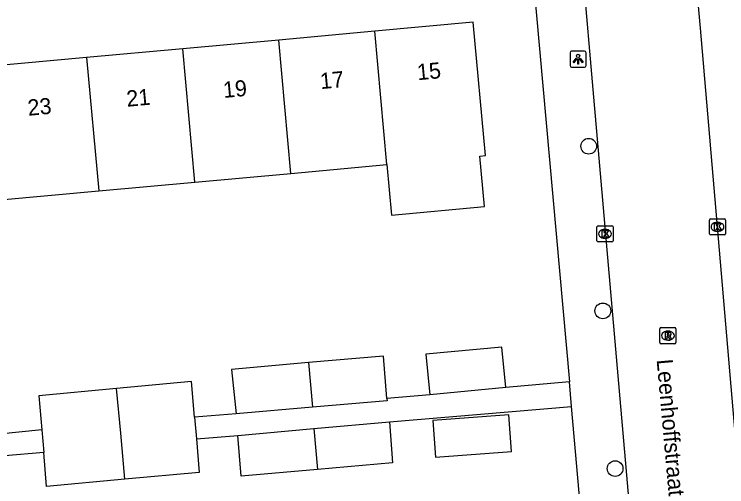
# Model space of a CAD drawing. Extents: x 160557 to 161245, y 385330 to 386505.
# Drawn here: x 161028.26 to 161072.59, y 385585.88 to 385615.29 of the extents above; entities that cross this region are included whole.
import ezdxf

# ---------------------------------------------------------------- set-up
doc = ezdxf.new("R2010")
doc.units = 0
for name, color, linetype in [('IMGEO_Boom', 7, 'Continuous'), ('IMGEO_Kolk', 7, 'Continuous'), ('IMGEO_Lichtpunt', 7, 'Continuous'), ('IMGEO_Openbare_ruimte_label', 7, 'Continuous'), ('IMGEO_Pand', 7, 'Continuous'), ('IMGEO_Pand_nummerreeks', 7, 'Continuous'), ('IMGEO_Rijbaan_lokaal_open', 7, 'Continuous'), ('IMGEO_Rioolput', 7, 'Continuous'), ('IMGEO_Voetpad_open', 7, 'Continuous')]:
    doc.layers.add(name, color=color, linetype=linetype)

msp = doc.modelspace()

# ---------------------------------------------------------------- linework, layer by layer
at = {"layer": 'IMGEO_Boom'}
for centre in [(161064.001, 385607.074), (161064.879, 385596.824), (161065.645, 385587.006)]:
    msp.add_circle(centre, 0.489, dxfattribs=at)
at = {"layer": 'IMGEO_Kolk'}
for p, q in [((161071.59, 385602.554), (161072.442, 385602.554)), ((161064.59, 385602.121), (161065.442, 385602.121)), ((161071.515, 385601.628), (161071.515, 385602.48)), ((161072.003, 385602.334), (161072.028, 385602.334)), ((161072.516, 385602.48), (161072.516, 385601.628)), ((161064.515, 385601.195), (161064.515, 385602.047)), ((161065.003, 385601.901), (161065.028, 385601.901)), ((161065.516, 385602.047), (161065.516, 385601.195)), ((161072.026, 385601.774), (161072.001, 385601.774)), ((161065.026, 385601.341), (161065.001, 385601.341)), ((161072.442, 385601.554), (161071.59, 385601.554)), ((161065.442, 385601.121), (161064.59, 385601.121))]:
    msp.add_line(p, q, dxfattribs=at)
for points in [[(161071.59, 385602.554), (161072.442, 385602.554)], [(161064.59, 385602.121), (161065.442, 385602.121)], [(161071.515, 385601.628), (161071.515, 385602.48)], [(161071.836, 385602.254), (161071.959, 385602.254), (161071.959, 385602.103), (161072.089, 385602.254), (161072.253, 385602.254), (161072.107, 385602.103), (161072.26, 385601.854), (161072.108, 385601.854), (161072.023, 385602.018), (161071.959, 385601.951), (161071.959, 385601.854), (161071.836, 385601.854), (161071.836, 385602.254)], [(161072.516, 385602.48), (161072.516, 385601.628)], [(161064.515, 385601.195), (161064.515, 385602.047)], [(161064.836, 385601.821), (161064.959, 385601.821), (161064.959, 385601.67), (161065.089, 385601.821), (161065.253, 385601.821), (161065.107, 385601.67), (161065.26, 385601.421), (161065.108, 385601.421), (161065.023, 385601.585), (161064.959, 385601.518), (161064.959, 385601.421), (161064.836, 385601.421), (161064.836, 385601.821)], [(161065.516, 385602.047), (161065.516, 385601.195)], [(161072.442, 385601.554), (161071.59, 385601.554)], [(161065.442, 385601.121), (161064.59, 385601.121)]]:
    msp.add_lwpolyline(points, dxfattribs=at)
for centre, start, end in [((161071.592, 385602.478), 91.552, 178.448), ((161071.592, 385602.478), 91.552, 178.448), ((161072.44, 385602.478), 1.552, 88.448), ((161072.44, 385602.478), 1.552, 88.448), ((161064.592, 385602.045), 91.552, 178.448), ((161064.592, 385602.045), 91.552, 178.448), ((161065.44, 385602.045), 1.552, 88.448), ((161065.44, 385602.045), 1.552, 88.448), ((161071.592, 385601.63), 181.552, 268.448), ((161071.592, 385601.63), 181.552, 268.448), ((161072.44, 385601.63), 271.552, 358.448), ((161072.44, 385601.63), 271.552, 358.448), ((161064.592, 385601.197), 181.552, 268.448), ((161064.592, 385601.197), 181.552, 268.448), ((161065.44, 385601.197), 271.552, 358.448), ((161065.44, 385601.197), 271.552, 358.448)]:
    msp.add_arc(centre, 0.0765, start, end, dxfattribs=at)
for centre, major_axis, ratio, start_param, end_param in [((161072.002, 385602.054), (-0.387, 0.002), 0.722429, 4.712389, 7.853982), ((161072.027, 385602.054), (-0.39, 0.002), 0.717154, 1.570796, 4.712389), ((161065.002, 385601.621), (-0.387, 0.002), 0.722429, 4.712389, 7.853982), ((161065.027, 385601.621), (-0.39, 0.002), 0.717154, 1.570796, 4.712389)]:
    msp.add_ellipse(centre, major_axis=major_axis, ratio=ratio, start_param=start_param, end_param=end_param, dxfattribs=at)
at = {"layer": 'IMGEO_Lichtpunt'}
for p, q in [((161062.842, 385612.899), (161062.842, 385612.092)), ((161062.842, 385612.899), (161062.842, 385612.092)), ((161063.744, 385612.994), (161062.936, 385612.994)), ((161063.744, 385612.994), (161062.936, 385612.994)), ((161063.838, 385612.092), (161063.838, 385612.899)), ((161063.838, 385612.092), (161063.838, 385612.899)), ((161062.936, 385611.998), (161063.744, 385611.998)), ((161062.936, 385611.998), (161063.744, 385611.998))]:
    msp.add_line(p, q, dxfattribs=at)
for points in [[(161063.216, 385612.563), (161063.255, 385612.535), (161063.067, 385612.273), (161063.029, 385612.3), (161063.216, 385612.563)], [(161063.318, 385612.515), (161063.365, 385612.515), (161063.365, 385612.193), (161063.318, 385612.193), (161063.318, 385612.515)], [(161063.428, 385612.535), (161063.466, 385612.562), (161063.653, 385612.3), (161063.614, 385612.272), (161063.428, 385612.535)]]:
    msp.add_lwpolyline(points, dxfattribs=at)
msp.add_circle((161063.341, 385612.697), 0.0994, dxfattribs=at)
for centre, start, end in [((161062.936, 385612.899), 90, 180), ((161062.936, 385612.899), 90, 180), ((161063.744, 385612.899), 0, 90), ((161063.744, 385612.899), 0, 90), ((161062.936, 385612.092), 180, 270), ((161062.936, 385612.092), 180, 270), ((161063.744, 385612.092), 270, 0), ((161063.744, 385612.092), 270, 360)]:
    msp.add_arc(centre, 0.0946, start, end, dxfattribs=at)
at = {"layer": 'IMGEO_Pand'}
for points in [[(161051.45, 385605.928), (161051.737, 385602.788), (161057.51, 385603.315), (161057.223, 385606.455), (161057.573, 385606.487), (161056.815, 385614.79), (161050.692, 385614.231)], [(161050.692, 385614.231), (161044.717, 385613.686)], [(161051.45, 385605.928), (161050.692, 385614.231)], [(161044.717, 385613.686), (161038.741, 385613.14)], [(161045.475, 385605.383), (161044.717, 385613.686)], [(161038.741, 385613.14), (161032.766, 385612.595)], [(161039.499, 385604.837), (161038.741, 385613.14)], [(161032.766, 385612.595), (161026.646, 385612.036), (161027.404, 385603.733), (161033.524, 385604.292)], [(161032.766, 385612.595), (161033.524, 385604.292)], [(161045.475, 385605.383), (161051.45, 385605.928)], [(161039.499, 385604.837), (161045.475, 385605.383)], [(161033.524, 385604.292), (161039.499, 385604.837)], [(161058.836, 385592.052), (161058.597, 385594.569), (161053.877, 385594.122), (161054.119, 385591.605)], [(161051.447, 385591.378), (161051.224, 385594.011), (161046.558, 385593.602)], [(161046.558, 385593.602), (161041.77, 385593.183), (161042.07, 385590.415)], [(161046.558, 385593.602), (161046.811, 385590.827)], [(161039.481, 385590.199), (161039.295, 385592.43), (161034.632, 385591.993)], [(161034.632, 385591.993), (161029.79, 385591.539), (161029.972, 385589.424)], [(161035.148, 385586.339), (161034.898, 385589.206), (161034.632, 385591.993)], [(161058.836, 385592.052), (161054.119, 385591.605)], [(161051.447, 385591.378), (161051.46, 385591.23), (161046.811, 385590.827)], [(161046.811, 385590.827), (161042.07, 385590.415)], [(161039.481, 385590.199), (161039.592, 385588.861)], [(161054.301, 385589.995), (161054.474, 385587.717), (161059.199, 385588.072), (161059.028, 385590.35), (161054.301, 385589.995)], [(161046.908, 385589.495), (161051.61, 385589.91)], [(161051.61, 385589.91), (161051.801, 385587.363), (161047.129, 385586.954)], [(161029.972, 385589.424), (161030.094, 385588.003)], [(161042.161, 385589.075), (161046.908, 385589.495)], [(161046.908, 385589.495), (161047.129, 385586.954)], [(161039.592, 385588.861), (161039.767, 385586.767), (161035.148, 385586.339)], [(161047.129, 385586.954), (161042.372, 385586.538), (161042.161, 385589.075)], [(161035.148, 385586.339), (161030.276, 385585.888), (161030.094, 385588.003)]]:
    msp.add_lwpolyline(points, dxfattribs=at)
at = {"layer": 'IMGEO_Rijbaan_lokaal_open'}
for points in [[(161070.591, 385618.12), (161070.675, 385617.407), (161070.927, 385614.424), (161074.538, 385572.239)], [(161071.555, 385527.133), (161071.554, 385527.151), (161071.552, 385527.169), (161064.234, 385611.073), (161063.712, 385617.074), (161063.655, 385617.485)]]:
    msp.add_lwpolyline(points, dxfattribs=at)
at = {"layer": 'IMGEO_Rioolput'}
for p, q in [((161068.429, 385594.856), (161068.429, 385595.708)), ((161068.504, 385595.782), (161069.356, 385595.782)), ((161068.917, 385595.562), (161068.942, 385595.562)), ((161069.43, 385595.708), (161069.43, 385594.856)), ((161068.94, 385595.002), (161068.915, 385595.002)), ((161069.356, 385594.782), (161068.504, 385594.782))]:
    msp.add_line(p, q, dxfattribs=at)
for points in [[(161068.429, 385594.856), (161068.429, 385595.708)], [(161068.504, 385595.782), (161069.356, 385595.782)], [(161069.018, 385595.48), (161068.766, 385595.482), (161068.766, 385595.082)], [(161069.43, 385595.708), (161069.43, 385594.856)], [(161068.766, 385595.082), (161068.89, 385595.082), (161068.89, 385595.244), (161068.901, 385595.244)], [(161068.944, 385595.401), (161068.89, 385595.401), (161068.89, 385595.32)], [(161068.89, 385595.32), (161068.942, 385595.32)], [(161068.948, 385595.215), (161069.019, 385595.082), (161069.159, 385595.082), (161069.094, 385595.208)], [(161069.356, 385594.782), (161068.504, 385594.782)]]:
    msp.add_lwpolyline(points, dxfattribs=at)
for centre, radius, start, end in [((161068.506, 385595.706), 0.0765, 91.552, 178.448), ((161068.506, 385595.706), 0.0765, 91.552, 178.448), ((161069.017, 385595.37), 0.109, 350.3612, 89.416), ((161069.354, 385595.706), 0.0765, 1.552, 88.448), ((161069.354, 385595.706), 0.0765, 1.552, 88.448), ((161068.9, 385595.191), 0.0533, 26.0293, 88.6989), ((161068.926, 385595.509), 0.19, 274.7715, 282.9687), ((161068.95, 385595.305), 0.0964, 77.0061, 93.1865), ((161068.964, 385595.362), 0.0378, 276.6634, 79.6772), ((161069.015, 385595.37), 0.112, 277.5842, 350.9817), ((161068.999, 385595.155), 0.108, 29.5134, 73.7905), ((161068.506, 385594.858), 0.0765, 181.552, 268.448), ((161068.506, 385594.858), 0.0765, 181.552, 268.448), ((161069.354, 385594.858), 0.0765, 271.552, 358.448), ((161069.354, 385594.858), 0.0765, 271.552, 358.448)]:
    msp.add_arc(centre, radius, start, end, dxfattribs=at)
for centre, major_axis, ratio, start_param, end_param in [((161068.916, 385595.282), (-0.387, 0.002), 0.722429, 4.712389, 7.853982), ((161068.941, 385595.282), (-0.39, 0.002), 0.717154, 1.570796, 4.712389)]:
    msp.add_ellipse(centre, major_axis=major_axis, ratio=ratio, start_param=start_param, end_param=end_param, dxfattribs=at)
at = {"layer": 'IMGEO_Voetpad_open'}
for points in [[(161060.535, 385617.772), (161062.796, 385592.405)], [(161029.972, 385589.424), (161027.299, 385589.149), (161024.73, 385616.897)], [(161062.796, 385592.405), (161058.836, 385592.052)], [(161062.932, 385590.876), (161062.796, 385592.405)], [(161054.119, 385591.605), (161051.447, 385591.378)], [(161051.61, 385589.91), (161062.932, 385590.876)], [(161064.786, 385570.078), (161062.932, 385590.876)], [(161042.07, 385590.415), (161039.481, 385590.199)], [(161039.592, 385588.861), (161042.161, 385589.075)], [(161030.094, 385588.003), (161027.674, 385587.795)]]:
    msp.add_lwpolyline(points, dxfattribs=at)

# ---------------------------------------------------------------- texts
at = {"layer": 'IMGEO_Openbare_ruimte_label'}
msp.add_text('Leenhoffstraat', height=1, rotation=275.1062, dxfattribs=at).set_placement((161068.225, 385593.78))
at = {"layer": 'IMGEO_Pand_nummerreeks'}
for s, rotation, p in [('15', 5.2139, (161053.365, 385611.181)), ('17', 5.2158, (161047.33, 385610.63)), ('19', 5.2158, (161041.296, 385610.079)), ('21', 5.2158, (161035.284, 385609.53)), ('23', 5.2158, (161029.138, 385608.969))]:
    msp.add_text(s, height=1, rotation=rotation, dxfattribs=at).set_placement(p)

doc.saveas('drawing.dxf')
